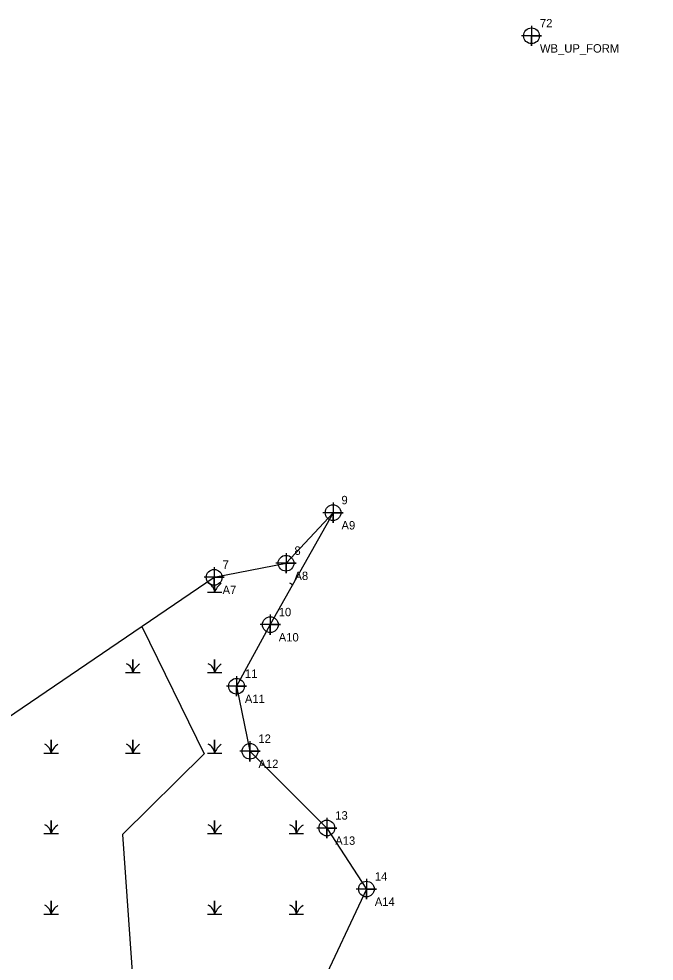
# Model space of a CAD drawing. Extents: x 2678633 to 2679425, y 623836 to 624637.
# Drawn here: x 2679228 to 2679417, y 624356.4 to 624636.7 of the extents above; entities that cross this region are included whole.
import ezdxf

# ---------------------------------------------------------------- set-up
doc = ezdxf.new("R2010")
doc.units = 0
for name, color, linetype in [('Default', 7, 'Continuous'), ('Exist Environmental Wetland Boundary', 7, 'Continuous'), ('Exist Environmental Wetland Boundary Cogo Comment', 7, 'Continuous'), ('Exist Environmental Wetland Boundary Cogo Number', 7, 'Continuous'), ('Exist Environmental Wetland Boundary Cogo Point CELL', 7, 'Continuous'), ('Exist Hydro Swamp or Marsh', 7, 'Continuous')]:
    doc.layers.add(name, color=color, linetype=linetype)

msp = doc.modelspace()

# ---------------------------------------------------------------- linework, layer by layer
at = {"layer": 'Default'}
msp.add_lwpolyline([(2679380.55, 624634.71), (2679380.55, 624628.71), (2679380.55, 624631.71), (2679383.55, 624631.71), (2679377.55, 624631.71)], dxfattribs=at)
msp.add_circle((2679380.55, 624631.71), 2.34, dxfattribs=at)
at = {"layer": 'Exist Environmental Wetland Boundary'}
for points in [[(2678996.94, 624177.71), (2679033.89, 624182.51), (2679071.36, 624253.6), (2679114.38, 624321.81), (2679163.39, 624374.56), (2679217.13, 624423.71), (2679286.14, 624470.62), (2679307.52, 624474.8), (2679321.51, 624489.84), (2679302.84, 624456.53), (2679292.78, 624438.21), (2679296.8, 624418.87), (2679319.66, 624396.04), (2679331.43, 624377.88), (2679317.29, 624347.71), (2679323.72, 624307.13), (2679356.11, 624275.91), (2679393.07, 624264.72), (2679417.04, 624216.21)], [(2679264.64, 624456.01), (2679283.2, 624418.1), (2679258.89, 624394.15), (2679261.95, 624350.41), (2679290.83, 624321), (2679275.38, 624287.41), (2679310.58, 624254.61), (2679334.89, 624254.61), (2679397.97, 624181.63)]]:
    msp.add_lwpolyline(points, dxfattribs=at)
at = {"layer": 'Exist Environmental Wetland Boundary Cogo Point CELL'}
for points in [[(2679321.51, 624492.84), (2679321.51, 624486.84), (2679321.51, 624489.84), (2679324.51, 624489.84), (2679318.51, 624489.84)], [(2679307.52, 624477.8), (2679307.52, 624471.8), (2679307.52, 624474.8), (2679310.52, 624474.8), (2679304.52, 624474.8)], [(2679286.14, 624473.62), (2679286.14, 624467.62), (2679286.14, 624470.62), (2679289.14, 624470.62), (2679283.14, 624470.62)], [(2679302.84, 624459.53), (2679302.84, 624453.53), (2679302.84, 624456.53), (2679305.84, 624456.53), (2679299.84, 624456.53)], [(2679292.78, 624441.21), (2679292.78, 624435.21), (2679292.78, 624438.21), (2679295.78, 624438.21), (2679289.78, 624438.21)], [(2679296.8, 624421.87), (2679296.8, 624415.87), (2679296.8, 624418.87), (2679299.8, 624418.87), (2679293.8, 624418.87)], [(2679319.66, 624399.04), (2679319.66, 624393.04), (2679319.66, 624396.04), (2679322.66, 624396.04), (2679316.66, 624396.04)], [(2679331.43, 624380.88), (2679331.43, 624374.88), (2679331.43, 624377.88), (2679334.43, 624377.88), (2679328.43, 624377.88)]]:
    msp.add_lwpolyline(points, dxfattribs=at)
for centre in [(2679321.51, 624489.84), (2679307.52, 624474.8), (2679286.14, 624470.62), (2679302.84, 624456.53), (2679292.78, 624438.21), (2679296.8, 624418.87), (2679319.66, 624396.04), (2679331.43, 624377.88)]:
    msp.add_circle(centre, 2.34, dxfattribs=at)
at = {"layer": 'Exist Hydro Swamp or Marsh'}
for points in [[(2679284.11, 624466.22), (2679286.26, 624466.22), (2679286.26, 624468.28)], [(2679286.26, 624468.28), (2679286.26, 624466.22), (2679288.42, 624466.22)], [(2679259.8, 624442.27), (2679261.95, 624442.27), (2679261.95, 624446.21), (2679261.95, 624442.27), (2679264.1, 624442.27)], [(2679284.11, 624442.27), (2679286.26, 624442.27), (2679286.26, 624446.21), (2679286.26, 624442.27), (2679288.42, 624442.27)], [(2679235.49, 624418.32), (2679237.64, 624418.32), (2679237.64, 624422.26), (2679237.64, 624418.32), (2679239.79, 624418.32)], [(2679259.8, 624418.32), (2679261.95, 624418.32), (2679261.95, 624422.26), (2679261.95, 624418.32), (2679264.1, 624418.32)], [(2679284.11, 624418.32), (2679286.26, 624418.32), (2679286.26, 624422.26), (2679286.26, 624418.32), (2679288.42, 624418.32)], [(2679235.49, 624394.37), (2679237.64, 624394.37), (2679237.64, 624398.31), (2679237.64, 624394.37), (2679239.79, 624394.37)], [(2679284.11, 624394.37), (2679286.26, 624394.37), (2679286.26, 624398.31), (2679286.26, 624394.37), (2679288.42, 624394.37)], [(2679308.43, 624394.37), (2679310.58, 624394.37), (2679310.58, 624398.31), (2679310.58, 624394.37), (2679312.73, 624394.37)], [(2679235.49, 624370.42), (2679237.64, 624370.42), (2679237.64, 624374.36), (2679237.64, 624370.42), (2679239.79, 624370.42)], [(2679284.11, 624370.42), (2679286.26, 624370.42), (2679286.26, 624374.36), (2679286.26, 624370.42), (2679288.42, 624370.42)], [(2679308.43, 624370.42), (2679310.58, 624370.42), (2679310.58, 624374.36), (2679310.58, 624370.42), (2679312.73, 624370.42)]]:
    msp.add_lwpolyline(points, dxfattribs=at)
for centre, radius, start, end in [((2679283.2, 624466), 3.07, 4.1403, 67.535), ((2679290.83, 624464.7), 4.81, 122.1274, 161.6222), ((2679307.51, 624466), 3.07, 50.3366, 67.535), ((2679258.89, 624442.05), 3.07, 4.1403, 67.535), ((2679266.51, 624440.75), 4.81, 122.1274, 161.6222), ((2679283.2, 624442.05), 3.07, 4.1403, 67.535), ((2679290.83, 624440.75), 4.81, 122.1274, 161.6222), ((2679234.57, 624418.1), 3.07, 4.1403, 67.535), ((2679242.2, 624416.8), 4.81, 122.1274, 161.6222), ((2679258.89, 624418.1), 3.07, 4.1403, 67.535), ((2679266.51, 624416.8), 4.81, 122.1274, 161.6222), ((2679283.2, 624418.1), 3.07, 4.1403, 67.535), ((2679290.83, 624416.8), 4.81, 122.1274, 161.6222), ((2679234.57, 624394.15), 3.07, 4.1403, 67.535), ((2679242.2, 624392.85), 4.81, 122.1274, 161.6222), ((2679283.2, 624394.15), 3.07, 4.1403, 67.535), ((2679290.83, 624392.85), 4.81, 122.1274, 161.6222), ((2679307.51, 624394.15), 3.07, 4.1403, 67.535), ((2679315.14, 624392.85), 4.81, 122.1274, 161.6222), ((2679234.57, 624370.2), 3.07, 4.1403, 67.535), ((2679242.2, 624368.9), 4.81, 122.1274, 161.6222), ((2679283.2, 624370.2), 3.07, 4.1403, 67.535), ((2679290.83, 624368.9), 4.81, 122.1274, 161.6222), ((2679307.51, 624370.2), 3.07, 4.1403, 67.535), ((2679315.14, 624368.9), 4.81, 122.1274, 161.6222)]:
    msp.add_arc(centre, radius, start, end, dxfattribs=at)

# ---------------------------------------------------------------- texts
at = {"layer": 'Default'}
msp.add_text('WB_UP_FORM', height=2.5, dxfattribs=at).set_placement((2679383.05, 624626.71))
at = {"layer": 'Exist Environmental Wetland Boundary Cogo Comment'}
for s, p in [('A9', (2679324.01, 624484.84)), ('A8', (2679310.02, 624469.8)), ('A7', (2679288.64, 624465.62)), ('A10', (2679305.34, 624451.53)), ('A11', (2679295.28, 624433.21)), ('A12', (2679299.3, 624413.87)), ('A13', (2679322.16, 624391.04)), ('A14', (2679333.93, 624372.88))]:
    msp.add_text(s, height=2.5, dxfattribs=at).set_placement(p)
at = {"layer": 'Exist Environmental Wetland Boundary Cogo Number'}
for s, p in [('72', (2679383.05, 624634.21)), ('9', (2679324.01, 624492.34)), ('8', (2679310.02, 624477.3)), ('7', (2679288.64, 624473.12)), ('10', (2679305.34, 624459.03)), ('11', (2679295.28, 624440.71)), ('12', (2679299.3, 624421.37)), ('13', (2679322.16, 624398.54)), ('14', (2679333.93, 624380.38))]:
    msp.add_text(s, height=2.5, dxfattribs=at).set_placement(p)

doc.saveas('drawing.dxf')
